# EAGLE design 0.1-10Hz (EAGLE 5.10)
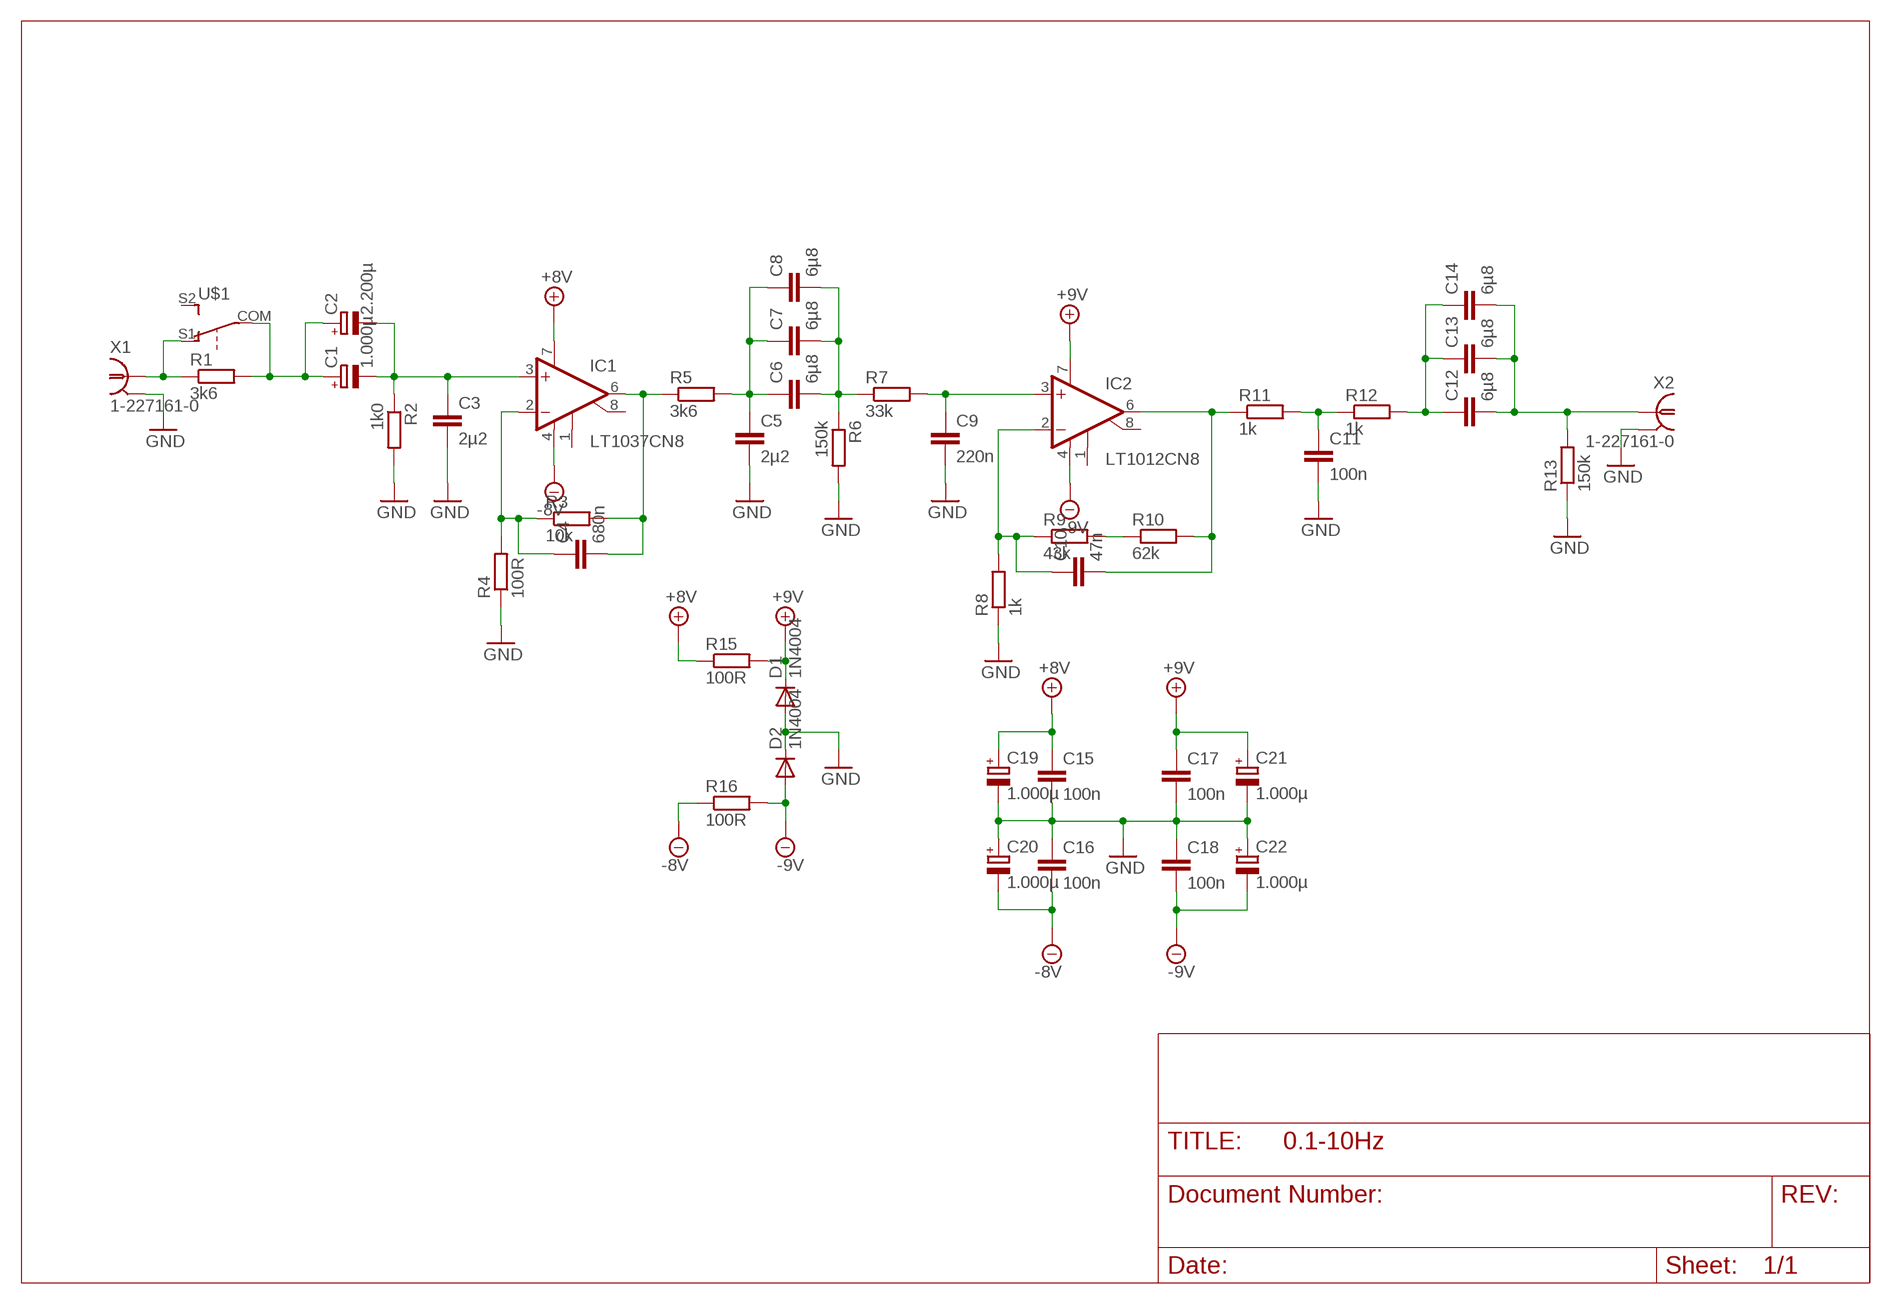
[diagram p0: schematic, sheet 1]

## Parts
C1  1.000µ  CPOL-EUE7.5-16  [E7,5-16]
C2  2.200µ  CPOL-EUE7.5-16  [E7,5-16]
C3  2µ2  C-EU050-075X075  [C050-075X075]
C4  680n  C-EU050-045X075  [C050-045X075]
C5  2µ2  C-EU050-075X075  [C050-075X075]
C6  6µ8  C-EU050-085X075  [C050-085X075]
C7  6µ8  C-EU050-085X075  [C050-085X075]
C8  6µ8  C-EU050-085X075  [C050-085X075]
C9  220n  C-EU050-030X075  [C050-030X075]
C10  47n  C-EU050-025X075  [C050-025X075]
C11  100n  C-EU050-025X075  [C050-025X075]
C12  6µ8  C-EU050-085X075  [C050-085X075]
C13  6µ8  C-EU050-085X075  [C050-085X075]
C14  6µ8  C-EU050-085X075  [C050-085X075]
C15  100n  C-EU050-025X075  [C050-025X075]
C16  100n  C-EU050-025X075  [C050-025X075]
C17  100n  C-EU050-025X075  [C050-025X075]
C18  100n  C-EU050-025X075  [C050-025X075]
C19  1.000µ  CPOL-EUE7.5-16  [E7,5-16]
C20  1.000µ  CPOL-EUE7.5-16  [E7,5-16]
C21  1.000µ  CPOL-EUE7.5-16  [E7,5-16]
C22  1.000µ  CPOL-EUE7.5-16  [E7,5-16]
D1  1N4004  [DO41-10]
D2  1N4004  [DO41-10]
IC1  LT1037CN8  [DIL08]
IC2  LT1012CN8  LT1037CN8  [DIL08]
R1  3k6  R-EU_0207/10  [0207/10]
R2  1k0  R-EU_0207/10  [0207/10]
R3  10k  R-EU_0207/10  [0207/10]
R4  100R  R-EU_0207/10  [0207/10]
R5  3k6  R-EU_0207/10  [0207/10]
R6  150k  R-EU_0207/10  [0207/10]
R7  33k  R-EU_0207/10  [0207/10]
R8  1k  R-EU_0207/10  [0207/10]
R9  43k  R-EU_0207/10  [0207/10]
R10  62k  R-EU_0207/10  [0207/10]
R11  1k  R-EU_0207/10  [0207/10]
R12  1k  R-EU_0207/10  [0207/10]
R13  150k  R-EU_0207/10  [0207/10]
R15  100R  R-EU_0207/10  [0207/10]
R16  100R  R-EU_0207/10  [0207/10]
U$1  MS-500AVT  [MS-500AVT]
X1  1-227161-0  [AMP_227161]
X2  1-227161-0  [AMP_227161]

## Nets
+8V: C15.1 C19.+ IC1.7(V+) R15.1
+9V: C17.1 C21.+ D1.C IC2.7(V+) R15.2
-8V: C16.2 C20.- IC1.4(V-) R16.1
-9V: C18.2 C22.- D2.A IC2.4(V-) R16.2
GND: C3.2 C5.2 C9.2 C11.2 C15.2 C16.1 C17.2 C18.1 C19.- C20.+ C21.- C22.+ D1.A D2.C R2.2 R4.1 R6.2 R8.1 R13.1 X1.2(GND) X2.2(GND)
N$1: C1.+ C2.+ R1.2 U$1.COM(P)
N$3: C4.1 IC1.2(-IN) R3.1 R4.2
N$4: C4.2 IC1.6(OUT) R3.2 R5.1
N$5: C5.1 C6.1 C7.1 C8.1 R5.2
N$6: C6.2 C7.2 C8.2 R6.1 R7.1
N$7: C9.1 IC2.3(+IN) R7.2
N$8: C10.1 IC2.2(-IN) R8.2 R9.1
N$9: C10.2 IC2.6(OUT) R10.2 R11.1
N$10: C11.1 R11.2 R12.1
N$11: C12.1 C13.1 C14.1 R12.2
N$12: C12.2 C13.2 C14.2 R13.2 X2.1
N$13: R9.2 R10.1
N$15: R1.1 U$1.S1(O) X1.1
N$16: C1.- C2.- C3.1 IC1.3(+IN) R2.1
Unconnected: IC1.1(CMP1) IC1.8(CMP2) IC2.1(CMP1) IC2.8(CMP2) U$1.S2(S)

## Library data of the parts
C1 C2 C19-C22 = rcl:CPOL-EU: POLARIZED CAPACITOR, European symbol
C3-C18 = rcl:C-EU: CAPACITOR, European symbol
D1 D2 = diode:1N4004: DIODE
IC1 IC2 = linear:LT10*: Low Noise, High Speed, Precision Operational Amplifiers Source: http://www.linear.com/pc/downloadDocument.do?navId=H0,C1,C1154,C1009,C1026,P1212,D2204
R1-R13 R15 R16 = rcl:R-EU_: RESISTOR, European symbol
U$1 = switch-misc:MS-500AVT
X1 X2 = con-coax:?227161*: JACK, RIGHT ANGLE, 50 OHM, PCB, BNC

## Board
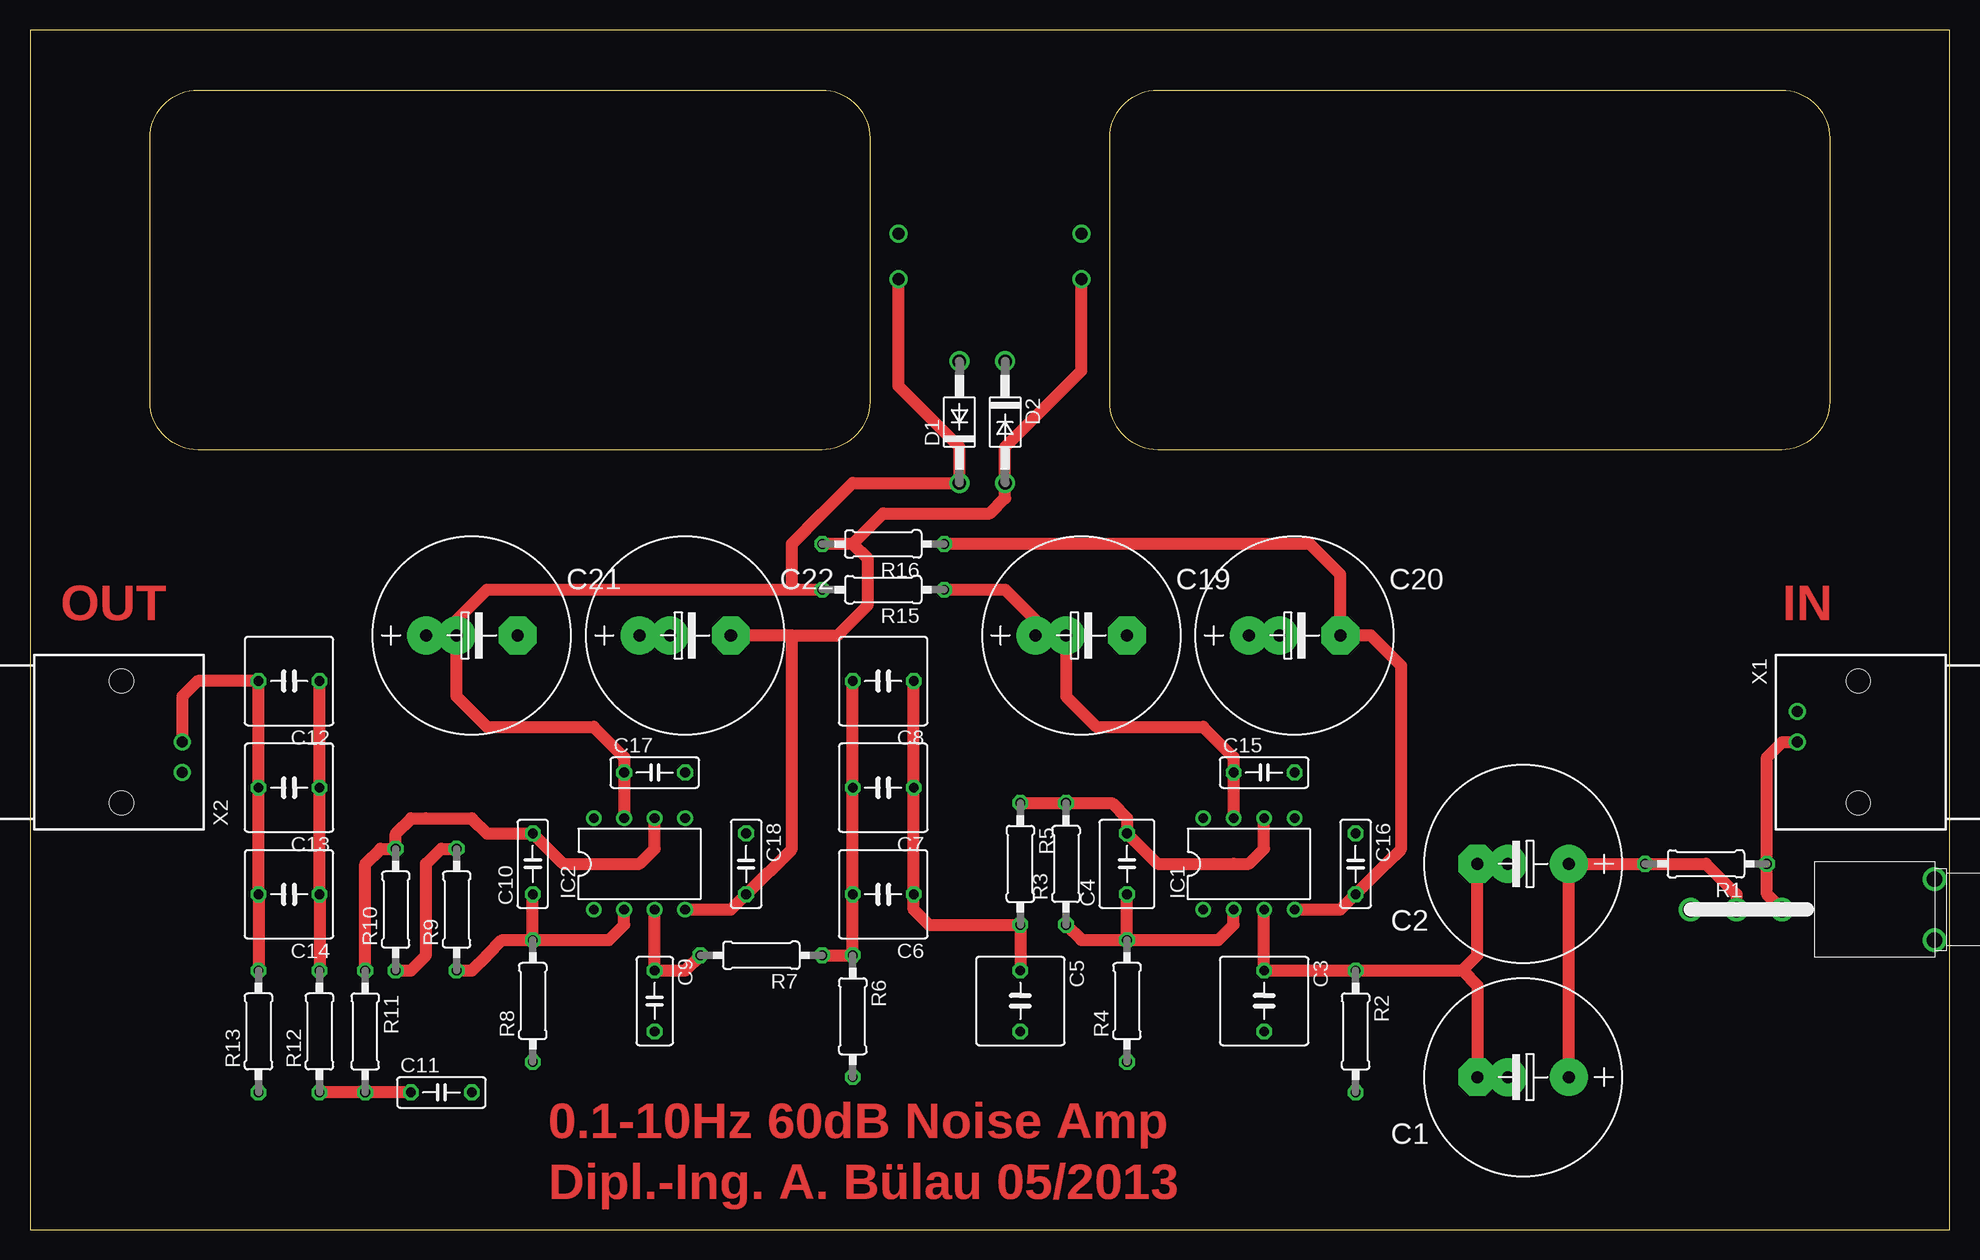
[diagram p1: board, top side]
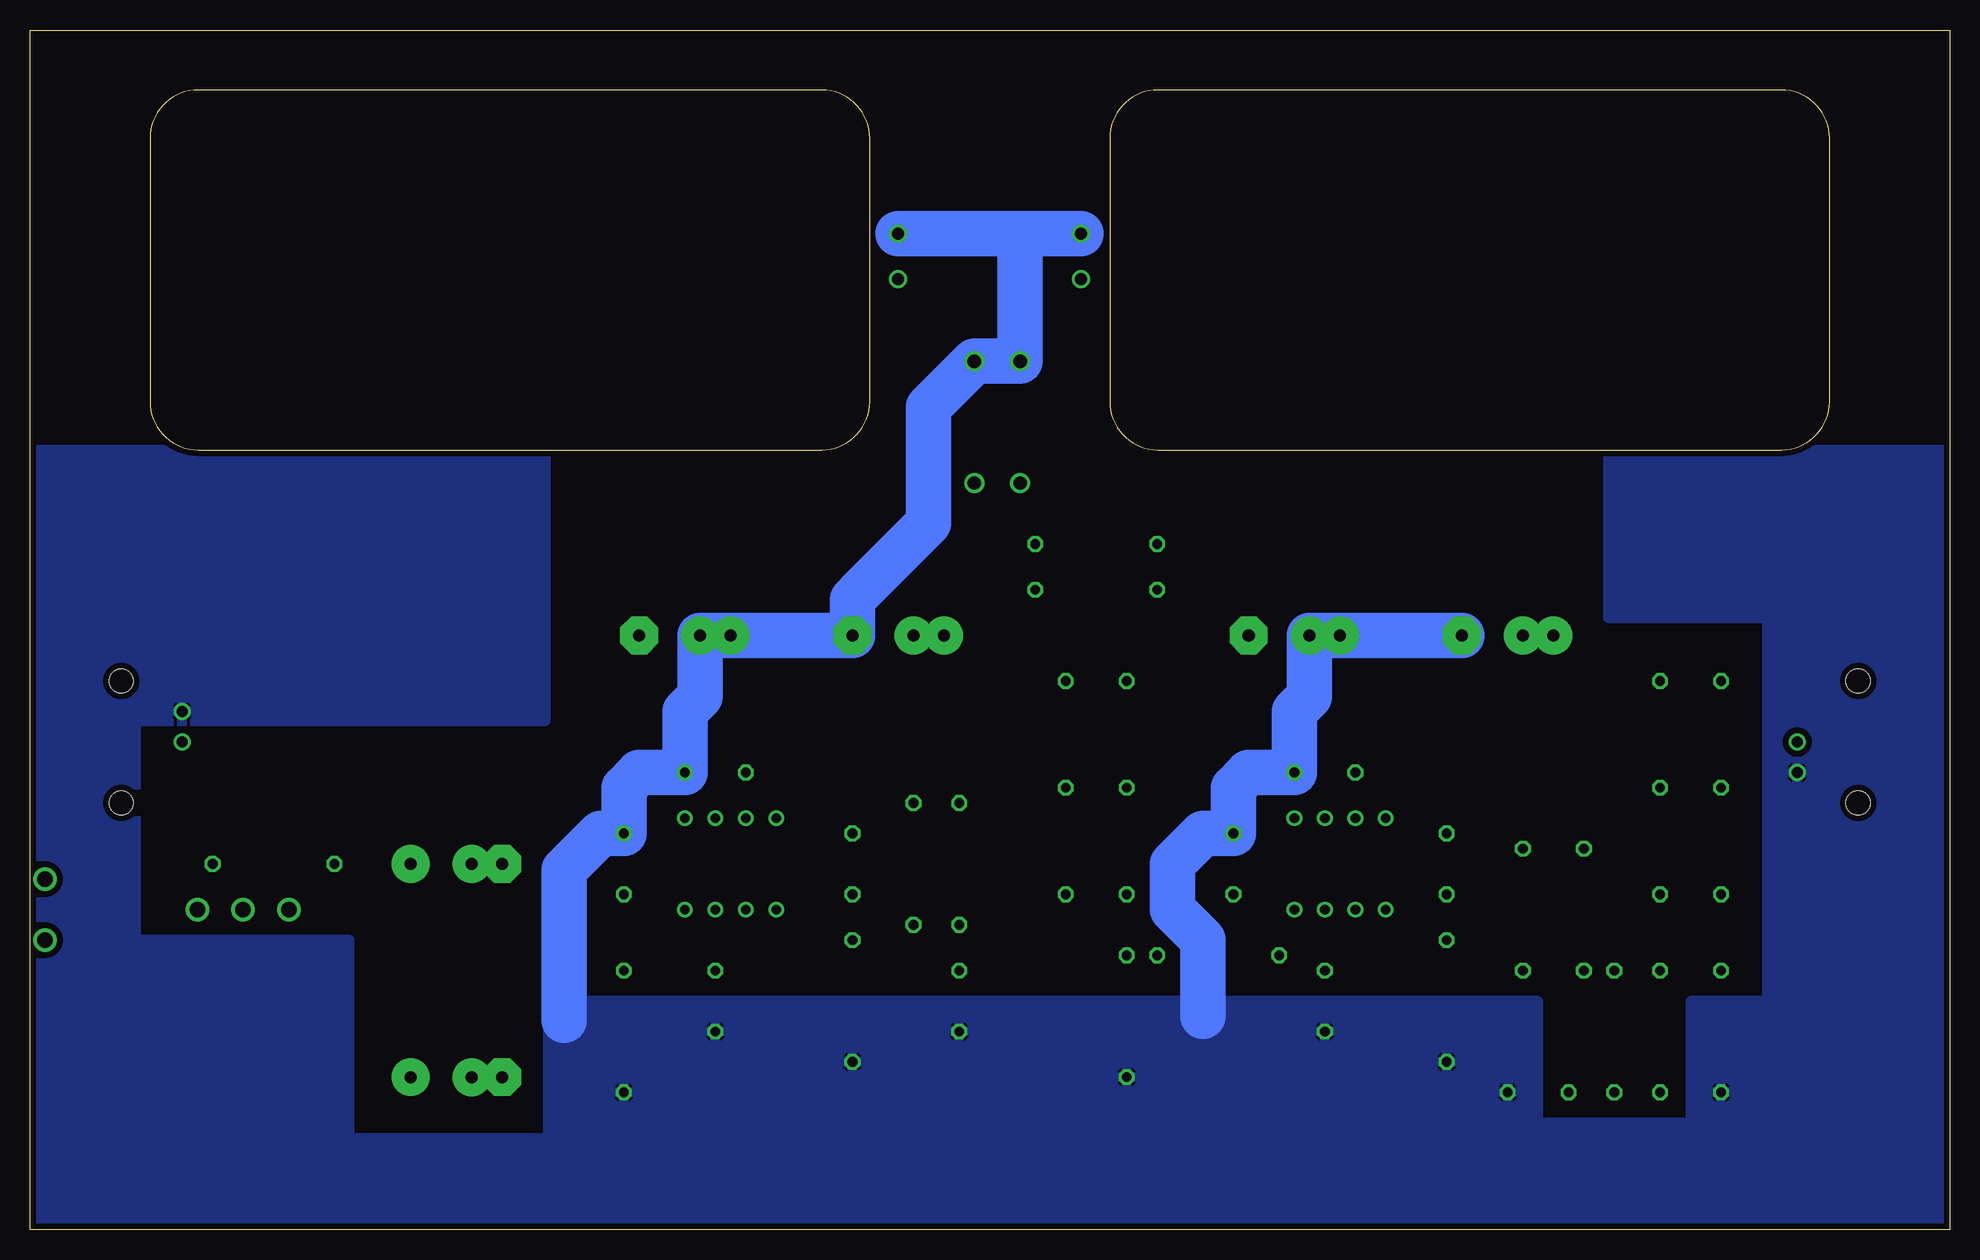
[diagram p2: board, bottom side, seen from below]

Size 160 x 100 mm. Coordinates in mm from the lower left corner, seen from the top.
Outline: 0,0 160,0 160,100 0,100 0,0
Outline: 10,91 arc-90 14,95 66,95 arc-90 70,91 70,69 arc-90 66,65 14,65 arc-90 10,69 10,91
Outline: 90,91 arc-90 94,95 146,95 arc-90 150,91 150,69 arc-90 146,65 94,65 arc-90 90,69 90,91
Copper layers (1*16): Top 0.035mm / dielectric 1.5mm / Bottom 0.035mm
Design rules "pcb-devboards_Standard": minimum track width 0.2mm, minimum drill 0.4mm, track to track 0.2mm, track to pad 0.2mm, pad to pad 0.2mm, via to via 0.2mm, smd to smd 0.2mm, copper to edge 0.4mm, drill to drill 0.2mm, minimum pad ring 0.25mm, minimum via ring 0.25mm, stop-mask expansion 0.1mm, vias tented up to drill 0mil, thermal gap 0.2mm

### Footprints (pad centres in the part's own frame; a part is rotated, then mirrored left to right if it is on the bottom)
E7,5-16 = drill 1.016 pad 3.15 round: + -3.81,0 | drill 1.016 pad 3.15 octagon: - 3.81,0
C050-075X075 = drill 0.813 octagon: 1 -2.54,0; 2 2.54,0
C050-045X075 = drill 0.813 octagon: 1 -2.54,0; 2 2.54,0
C050-085X075 = drill 0.813 octagon: 1 -2.54,0; 2 2.54,0
C050-030X075 = drill 0.813 octagon: 1 -2.54,0; 2 2.54,0
C050-025X075 = drill 0.813 octagon: 1 -2.54,0; 2 2.54,0
DO41-10 = drill 1.118 round: A 5.08,0; C -5.08,0
DIL08 = drill 0.813 pad 1.27 round: 1 -3.81,-3.81; 2 -1.27,-3.81; 3 1.27,-3.81; 4 3.81,-3.81; 5 3.81,3.81; 6 1.27,3.81; 7 -1.27,3.81; 8 -3.81,3.81
0207/10 = drill 0.813 octagon: 1 -5.08,0; 2 5.08,0
MS-500AVT = drill 1.3 round: COM 16.51,0; H1 0,2.54; H2 0,-2.54; S1 12.7,0; S2 20.32,0
AMP_227161 = drill 0.9 pad 1.27 round: 1 0,-5.08; 2 -2.54,-5.08 | hole 2: -5.08,0; 5.08,0

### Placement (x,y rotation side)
C1  124.46,12.7 180 top
C2  124.46,30.48 180 top
C3  102.87,19.05 270 top
C4  91.44,30.48 90 top
C5  82.55,19.05 270 top
C6  71.12,27.94 180 top
C7  71.12,36.83 180 top
C8  71.12,45.72 180 top
C9  52.07,19.05 270 top
C10  41.91,30.48 90 top
C11  34.29,11.43 0 top
C12  21.59,45.72 180 top
C13  21.59,36.83 180 top
C14  21.59,27.94 180 top
C15  102.87,38.1 0 top
C16  110.49,30.48 270 top
C17  52.07,38.1 0 top
C18  59.69,30.48 270 top
C19  87.63,49.53 0 top
C20  105.41,49.53 0 top
C21  36.83,49.53 0 top
C22  54.61,49.53 0 top
D1  77.47,67.31 90 top
D2  81.28,67.31 270 top
IC1  101.6,30.48 0 top
IC2  50.8,30.48 0 top
R1  139.7,30.48 180 top
R2  110.49,16.51 270 top
R3  86.36,30.48 90 top
R4  91.44,19.05 90 top
R5  82.55,30.48 270 top
R6  68.58,17.78 270 top
R7  60.96,22.86 180 top
R8  41.91,19.05 90 top
R9  35.56,26.67 90 top
R10  30.48,26.67 90 top
R11  27.94,16.51 270 top
R12  24.13,16.51 90 top
R13  19.05,16.51 90 top
R15  71.12,53.34 180 top
R16  71.12,57.15 180 top
U$1  158.75,26.67 180 top
X1  152.4,40.64 270 top
X2  7.62,40.64 90 top

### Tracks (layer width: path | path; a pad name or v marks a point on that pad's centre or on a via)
+8V  (via drill 1 pad 3.15)
  Top 1: IC1.7 C15.1 100.33,39.37 97.79,41.91 88.9,41.91 86.36,44.45 v86.36,49.53 C19.+ 83.82,50.8 81.28,53.34 R15.1
+9V  (via drill 1, 1 pad 3.15)
  Top 1: IC2.7 C17.1 49.53,39.37 46.99,41.91 38.1,41.91 35.56,44.45 v35.56,49.53 | v35.56,49.53 C21.+ | 63.5,53.34 38.1,53.34 35.56,50.8 v35.56,49.53 | 63.5,53.34 R15.2 | 63.5,53.34 63.5,57.15 66.04,59.69 68.58,62.23 D1.C 77.47,65.24 76.2,66.51 72.39,70.32 v72.39,79.21
-8V
  Top 1: IC1.4 109.22,26.67 C16.2 113.03,30.48 114.3,31.75 114.3,46.99 111.76,49.53 C20.- 109.22,54.61 106.68,57.15 R16.1
-9V  (via drill 1)
  Top 1: IC2.4 58.42,26.67 C18.2 63.5,31.75 63.5,49.53 | 68.58,57.15 R16.2 | 68.58,57.15 69.85,55.88 69.85,52.07 67.31,49.53 63.5,49.53 | 63.5,49.53 C22.- | 68.58,57.15 71.12,59.69 80.01,59.69 81.28,60.96 D2.A 81.28,65.24 82.55,66.51 87.63,71.59 v87.63,79.21
GND  (via drill 1, 1 pad 3.15)
  Bottom 3.8: C21.- C22.+ v53.34,49.53 53.34,44.45 54.61,43.18 C17.2 58.42,38.1 59.69,36.83 C18.1 62.23,33.02 64.77,30.48 64.77,26.67 62.23,24.13 62.23,17.78 | 115.46,17.43 115.46,30 112.44,33.02 C16.1 110.49,36.83 109.22,38.1 C15.2 105.41,43.18 104.14,44.45 v104.14,49.53 C20.+ C19.- 91.44,52.54 90.64,53.34 85.09,58.89 85.09,68.58 D2.C D1.A 77.47,83.02 | 77.47,83.02 v72.39,83.02 | 77.47,83.02 v87.63,83.02
  pour Bottom (isolate 0.5): 0,65 28.5,65 28.5,51 15.24,51 15.24,19.05 21.59,19.05 21.59,8.89 34.29,8.89 34.29,19.05 116.84,19.05 116.84,7.62 133.35,7.62 133.35,24.13 151.13,24.13 151.13,42.41 117,42.41 117,65 160.02,65 160.02,0 0,0
N$1
  Top 1: C1.+ C2.+ R1.2 139.7,30.48 142.24,27.94 U$1.COM
N$3
  Top 1: IC1.2 100.33,25.4 99.06,24.13 R4.2 | R4.2 C4.1 | R4.2 87.63,24.13 R3.1
N$4
  Top 1: IC1.6 102.87,31.75 101.6,30.48 100.33,30.48 93.98,30.48 C4.2 91.44,34.29 90.17,35.56 R3.2 R5.1
N$5
  Top 1: C8.1 C7.1 C6.1 73.66,26.67 74.93,25.4 R5.2 C5.1
N$6
  Top 1: C8.2 C7.2 C6.2 R6.1 R7.1
N$7
  Top 1: IC2.3 C9.1 54.61,21.59 R7.2
N$8
  Top 1: IC2.2 49.53,25.4 48.26,24.13 R8.2 | R8.2 C10.1 | R9.1 36.83,21.59 38.1,22.86 39.37,24.13 R8.2
N$9
  Top 1: IC2.6 52.07,31.75 50.8,30.48 44.45,30.48 C10.2 38.1,33.02 36.83,34.29 33.02,34.29 31.75,34.29 30.48,33.02 R10.2 29.21,31.75 27.94,30.48 R11.1
N$10
  Top 1: R12.1 R11.2 C11.1
N$11
  Top 1: C12.1 C13.1 C14.1 R12.2
N$12
  Top 1: X2.1 12.7,44.45 13.97,45.72 C12.2 C13.2 C14.2 R13.2
N$13
  Top 1: R9.2 34.29,31.75 33.02,30.48 33.02,26.67 33.02,24.13 33.02,22.86 31.75,21.59 R10.1
N$15
  Top 1: X1.1 146.05,40.64 144.78,39.37 R1.1 144.78,27.94 U$1.S1
N$16  (via drill 1 pad 3.15)
  Top 1: IC1.3 C3.1 109.22,21.59 R2.1 119.38,21.59 | 119.38,21.59 120.65,22.86 C2.- v123.19,30.48 | 119.38,21.59 120.65,20.32 C1.- v123.19,12.7

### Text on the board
Top: OUT | IN | 0.1-10Hz 60dB Noise Amp | Dipl.-Ing. A. Bülau 05/2013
